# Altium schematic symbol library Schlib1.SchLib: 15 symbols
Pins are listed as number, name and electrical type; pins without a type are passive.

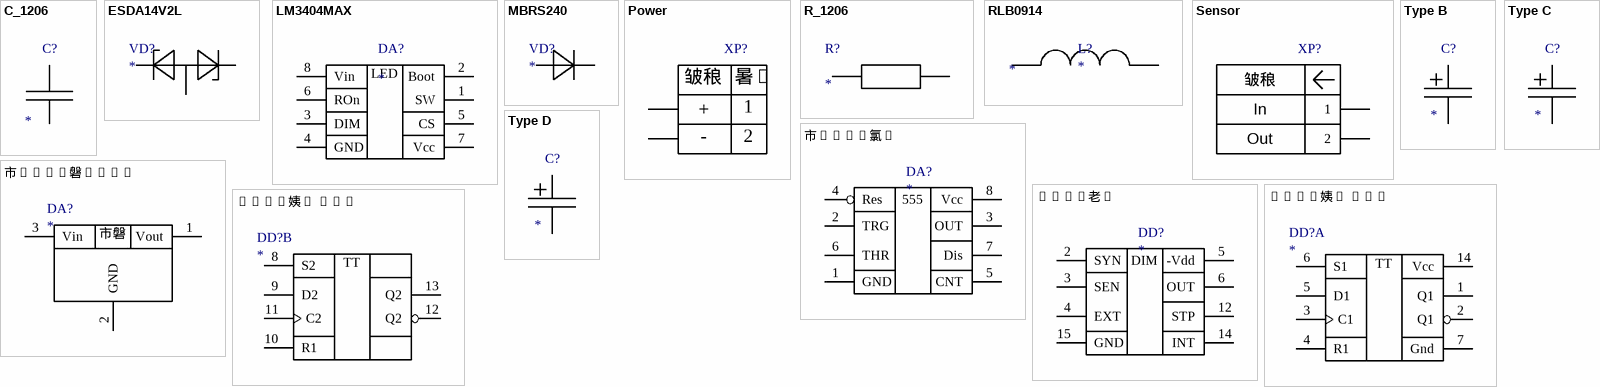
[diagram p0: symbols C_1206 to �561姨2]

## C_1206
designator C?
footprint RC_1206
pins: 1, 2

## ESDA14V2L
designator VD?
footprint SOT-23
pins: 1, 2, 3

## LM3404MAX
designator DA?
footprint SO-8
pins: 1 SW, 2 Boot, 3 DIM, 4 GND, 5 CS, 6 ROn, 7 Vcc, 8 Vin

## MBRS240
designator VD?
footprint D-64
pins: 1, 2

## Power
designator XP?  (value not drawn)
footprint 2EDGV-2P
pins: 1, 2

## R_1206
designator R?
footprint RC_1206
pins: 1, 2

## RLB0914
designator L?
footprint RLB0914
pins: 1, 2

## Sensor
designator XP?  (value not drawn)
footprint PLS-2
pins: 1, 2

## Type B
designator C?
footprint Type B
pins: 1, 2

## Type C
designator C?
footprint Type C
pins: 1, 2

## Type D
designator C?
footprint Type D
pins: 1, 2

## 市1006氯1
designator DA?
footprint DIP-8-RU
pins: 1 GND, 2 TRG, 3 OUT, 4 Res, 5 CNT, 6 THR, 7 Dis, 8 Vcc

## 市1157磐1502
designator DA?
footprint TO-92
pins: 1 Vout, 2 GND, 3 Vin

## �145老2
designator DD?
footprint DIP-16-RU
pins: 2 SYN, 3 SEN, 4 EXT, 5 -Vdd, 6 OUT, 12 STP, 14 INT, 15 GND

## �561姨2
designator DD?
footprint DIP-14-RU
part A pins: 1 Q1, 2 Q1, 3 C1, 4 R1, 5 D1, 6 S1, 7 Gnd, 14 Vcc
part B pins: 8 S2, 9 D2, 10 R1, 11 C2, 12 Q2, 13 Q2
